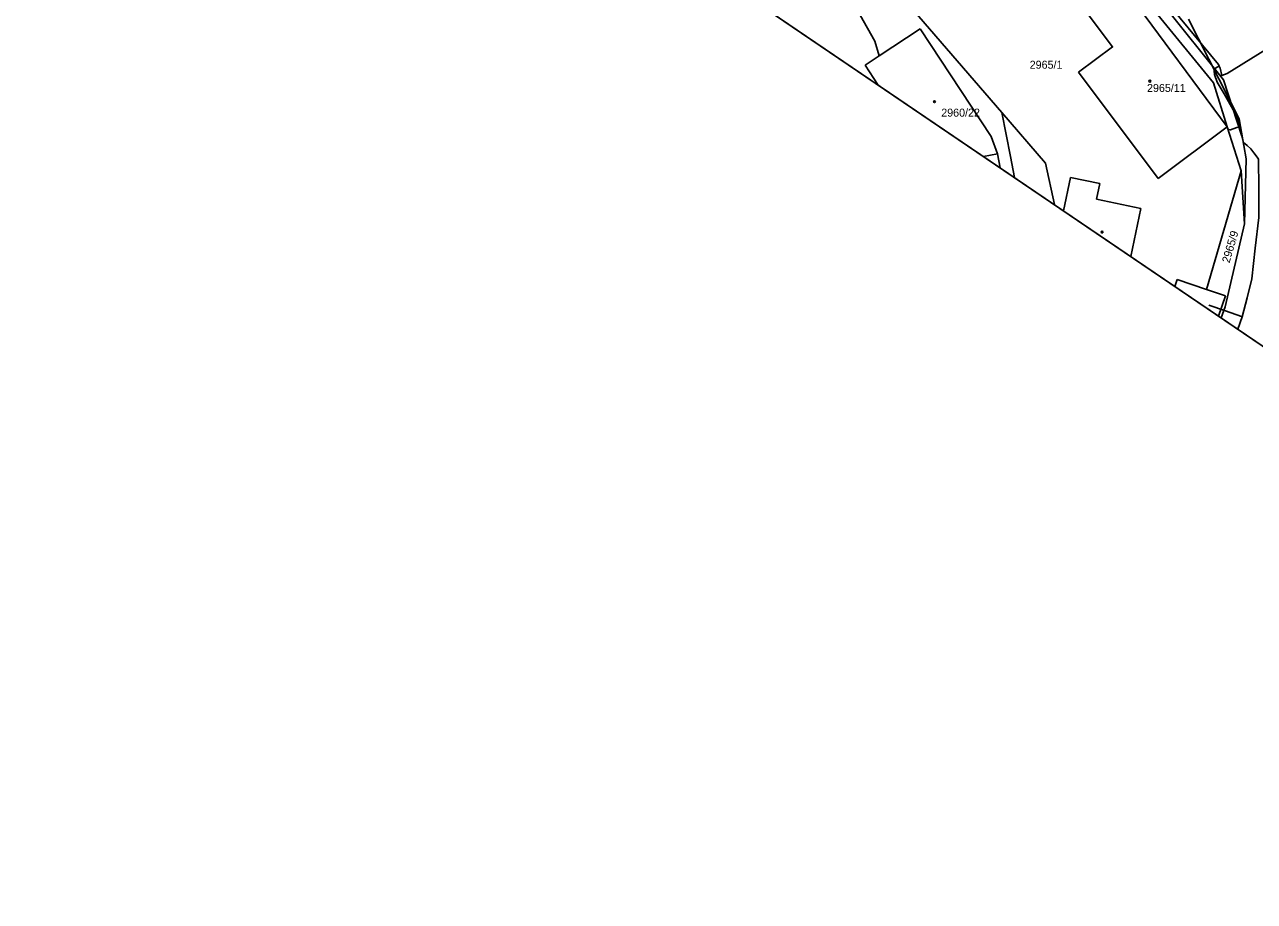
# Model space of a CAD drawing. Extents: x -621145 to -620023, y -1122866 to -1121971.
# Drawn here: x -620574.9 to -620344.4, y -1122865.7 to -1122701.2 of the extents above; entities that cross this region are included whole.
import ezdxf

# ---------------------------------------------------------------- set-up
doc = ezdxf.new("R2010")
doc.units = 0
for name, color, linetype in [('GasNet', 7, 'Continuous'), ('RÁMY', 7, 'Continuous'), ('VAS vodovod', 7, 'Continuous'), ('Vrstva 55', 7, 'Continuous'), ('Vrstva 57', 7, 'Continuous')]:
    doc.layers.add(name, color=color, linetype=linetype)

msp = doc.modelspace()

# ---------------------------------------------------------------- linework, layer by layer
at = {"layer": 'GasNet'}
for points in [[(-620545.62, -1122586.36), (-620544.33, -1122585.86), (-620529.1, -1122581.91), (-620527.88, -1122581.68), (-620501.79, -1122593.01), (-620500.52, -1122592.53), (-620484.13, -1122585.56), (-620478.57, -1122583.14), (-620474.2, -1122586.82), (-620449.91, -1122606.86), (-620450.02, -1122607.5), (-620458.5, -1122620.02), (-620458.8, -1122620.62), (-620432.06, -1122640.49), (-620425.64, -1122643.91), (-620417.98, -1122647.99), (-620389.11, -1122672.47), (-620361.34, -1122696.38), (-620351.16, -1122708.72), (-620351, -1122709.02), (-620350.83, -1122709.39), (-620350.53, -1122710.79), (-620349.5, -1122710.44), (-620336.68, -1122702.48)], [(-620351, -1122709.02), (-620351.62, -1122709.36), (-620351.95, -1122709.89), (-620351.89, -1122710.61), (-620351.38, -1122712.06), (-620350.09, -1122714.22), (-620348.14, -1122717.64), (-620346.99, -1122720.36), (-620347.15, -1122720.39), (-620347.67, -1122720.57), (-620348.9, -1122720.99), (-620349.23, -1122720.89), (-620349.32, -1122720.93)]]:
    msp.add_lwpolyline(points, dxfattribs=at)
at = {"layer": 'RÁMY'}
for points in [[(-621061.56, -1122093.92), (-620106.07, -1122742.82), (-620189.51, -1122865.67), (-621144.99, -1122216.77)], [(-620887.83, -1122211.9), (-620106.07, -1122742.82), (-620189.51, -1122865.67), (-620971.26, -1122334.75)]]:
    msp.add_lwpolyline(points, close=True, dxfattribs=at)
at = {"layer": 'VAS vodovod'}
for points in [[(-620346.78, -1122722.2), (-620350.17, -1122711.62), (-620361.5, -1122697.5), (-620361.99, -1122696.76), (-620371.19, -1122688.51), (-620418.43, -1122648.88), (-620439.22, -1122636.74), (-620439.29, -1122636.69), (-620439.37, -1122636.64), (-620460.46, -1122621.06), (-620460.7, -1122620.9), (-620459.95, -1122619.77), (-620451.51, -1122607.79), (-620450.89, -1122606.96), (-620476.53, -1122586.08), (-620476.53, -1122586.08), (-620476.87, -1122585.61)], [(-620347.51, -1122758.36), (-620346.67, -1122756.05), (-620345.79, -1122752.48), (-620344.9, -1122748.91), (-620344.25, -1122743.18), (-620343.6, -1122737.45), (-620343.6, -1122731.96), (-620343.61, -1122726.46), (-620343.74, -1122726.27), (-620343.87, -1122726.08), (-620344.48, -1122725.31), (-620345.09, -1122724.54), (-620345.76, -1122723.95), (-620346.43, -1122723.35), (-620346.44, -1122723.33), (-620346.48, -1122723.26), (-620346.53, -1122723.17), (-620346.66, -1122722.69), (-620346.78, -1122722.2)], [(-620346.67, -1122756.05), (-620346.82, -1122756), (-620349.82, -1122754.95), (-620352.97, -1122753.85)]]:
    msp.add_lwpolyline(points, dxfattribs=at)
at = {"layer": 'Vrstva 55'}
for p, q in [((-620391.77, -1122717.74), (-620434.88, -1122667.63)), ((-620370.13, -1122692.59), (-620349.5, -1122720.4)), ((-620415.57, -1122704.35), (-620421.46, -1122693.76)), ((-620407.04, -1122702.06), (-620414.76, -1122707.13)), ((-620393.75, -1122722.26), (-620407.04, -1122702.06)), ((-620347.29, -1122718.92), (-620356.78, -1122700.2)), ((-620414.76, -1122707.13), (-620415.57, -1122704.35)), ((-620414.76, -1122707.13), (-620417.37, -1122708.84)), ((-620417.37, -1122708.84), (-620414.89, -1122712.61)), ((-620377.36, -1122710.19), (-620362.45, -1122730.09)), ((-620391.77, -1122717.74), (-620383.57, -1122727.26)), ((-620390.13, -1122725.98), (-620391.77, -1122717.74)), ((-620349.5, -1122720.4), (-620362.45, -1122730.09)), ((-620349.5, -1122720.4), (-620346.9, -1122728.66)), ((-620345.94, -1122726.44), (-620347.29, -1122718.92)), ((-620392.56, -1122725.51), (-620393.75, -1122722.26)), ((-620395.15, -1122726.01), (-620392.56, -1122725.51)), ((-620392.56, -1122725.51), (-620392.06, -1122728.11)), ((-620389.35, -1122729.95), (-620390.13, -1122725.98)), ((-620381.9, -1122735.01), (-620383.57, -1122727.26)), ((-620346.26, -1122738.61), (-620345.94, -1122726.44)), ((-620346.9, -1122728.66), (-620353.41, -1122750.9)), ((-620346.26, -1122738.61), (-620346.9, -1122728.66)), ((-620378.87, -1122729.94), (-620380.18, -1122736.18)), ((-620378.87, -1122729.94), (-620373.38, -1122731.07)), ((-620373.38, -1122731.07), (-620373.97, -1122734.01)), ((-620373.97, -1122734.01), (-620365.7, -1122735.74)), ((-620365.7, -1122735.74), (-620367.58, -1122744.74)), ((-620349.91, -1122754.18), (-620346.26, -1122738.61)), ((-620358.86, -1122749.03), (-620359.31, -1122750.35)), ((-620358.86, -1122749.03), (-620353.41, -1122750.9)), ((-620353.41, -1122750.9), (-620349.8, -1122752.13)), ((-620351.12, -1122755.91), (-620349.8, -1122752.13)), ((-620350.63, -1122756.24), (-620349.91, -1122754.18))]:
    msp.add_line(p, q, dxfattribs=at)
for points in [[(-620432.38, -1122643.03), (-620419.73, -1122650.41), (-620372.55, -1122689.97), (-620363.06, -1122698.75), (-620352.08, -1122712.18), (-620349.5, -1122720.4)], [(-620377.36, -1122710.19), (-620370.99, -1122705.44), (-620376.85, -1122697.59)]]:
    msp.add_lwpolyline(points, dxfattribs=at)
at = {"layer": 'Vrstva 57'}
for centre in [(-620363.99, -1122711.85), (-620404.37, -1122715.7), (-620372.96, -1122740.15)]:
    msp.add_circle(centre, 0.175, dxfattribs=at)

# ---------------------------------------------------------------- texts
for s, p in [('2965/1', (-620386.52, -1122709.52)), ('2965/11', (-620364.53, -1122713.88)), ('2960/22', (-620403.1, -1122718.51))]:
    msp.add_text(s, height=1.5, dxfattribs=at).set_placement(p)
msp.add_text('2965/9', height=1.5, rotation=73.8221, dxfattribs=at).set_placement((-620349.08, -1122746.06))

doc.saveas('drawing.dxf')
